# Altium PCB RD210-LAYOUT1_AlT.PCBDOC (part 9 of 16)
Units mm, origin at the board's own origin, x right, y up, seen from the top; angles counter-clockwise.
Board outline 330 x 300 mm, 6 copper layers (TOP, Mid-Layer 1, Mid-Layer 2, Mid-Layer 3, Mid-Layer 4, BOTTOM), stack 1.422 mm thick; 981 components, 463 nets, 2326 pads, 12534 vias.
Unrouted connection lines stored in the file: 6.
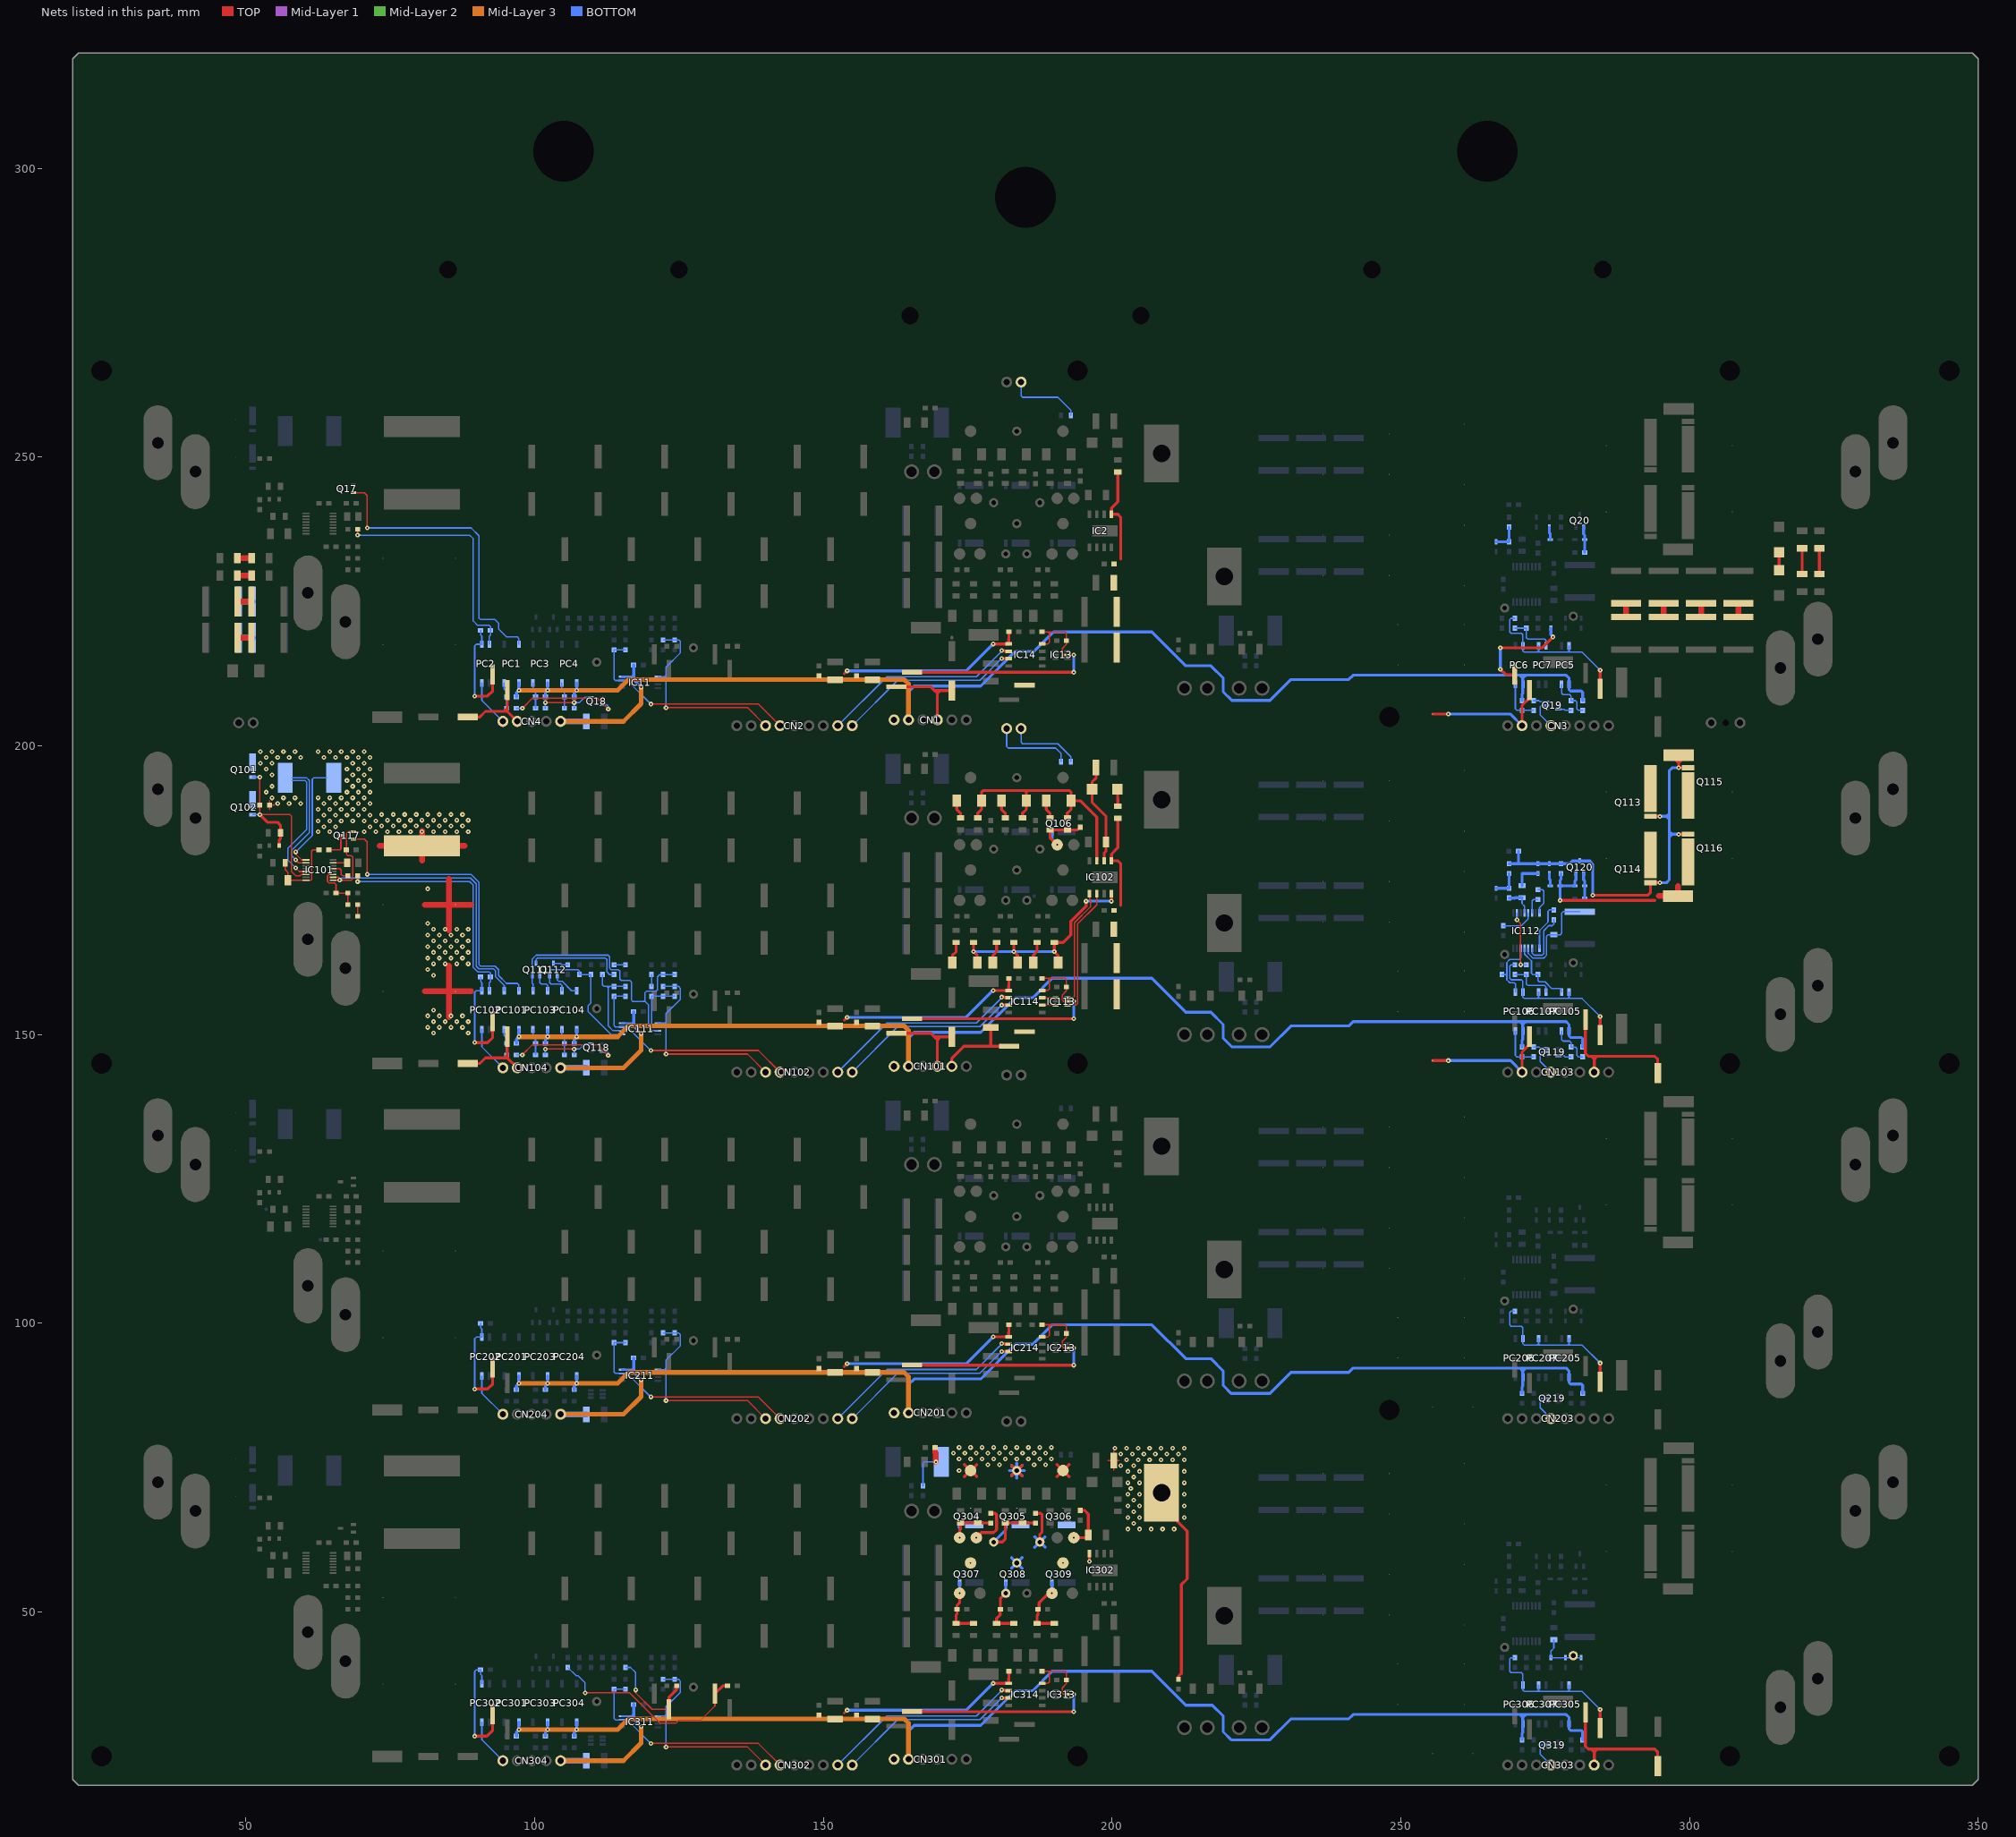
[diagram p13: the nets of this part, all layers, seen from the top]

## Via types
v1: diameter 0.8, hole 0.3, TOP to BOTTOM, 12534 vias

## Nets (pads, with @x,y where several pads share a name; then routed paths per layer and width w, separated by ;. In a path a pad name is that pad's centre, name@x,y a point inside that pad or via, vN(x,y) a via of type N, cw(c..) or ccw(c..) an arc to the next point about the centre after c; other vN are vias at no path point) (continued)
N00300323: PC1.6 Q17.1 | length 52.4
  TOP w0.25: Q17.1@68.55,243.85 Q17.1@68.6,243.85 70.525,243.85 71,243.375 v1(71,237.75)
  BOTTOM w0.25: v1(71,237.75) 89,237.75 90.375,236.375 90.375,222.125 90.625,221.875 93.125,221.875 93.75,221.25 93.75,220.25 95.125,218.875 97.02,218.875 97.27,218.625 PC1.6@97.27,217.6
N00300324: PC1.3 R66.1 R67.1 | length 4.6
  BOTTOM w0.25: PC1.3@94.715,210.9 94.715,209.91 95.15,209.475 R66.1@95.15,208.5 R67.1@95.15,206.5
N00300328: Q18.6 R67.2 | length 19
  TOP w0.25: v1(97.875,206.5) 99.625,208.25 110.875,208.25 v1(112.75,206.375)
  BOTTOM w0.25: R67.2@96.85,206.5 v1(97.875,206.5) ; Q18.6@111.775,207.1 112.5,207.1 112.75,206.85 v1(112.75,206.375)
N00300330: Q18.3 R69.1 R72.1 | length 10.2
  TOP w0.25: v1(101.85,207.5) v1(106.85,207.5)
  BOTTOM w0.25: R69.1@101.85,206.5 v1(101.85,207.5) ; R72.1@106.85,206.5 v1(106.85,207.5) 107.75,207.5 108.65,208.4 Q18.3@109.725,208.4
N00300332: PC2.2 R70.2 R71.1 | length 42.1
  TOP w0.25: v1(69.35,236.5) R70.2@69.35,237.5
  BOTTOM w0.25: v1(69.35,236.5) 88.75,236.5 89.375,235.875 89.375,221.625 90.125,220.875 92.15,220.875 92.35,220.675 R71.1@92.35,220 92.35,219.2 92.15,219 PC2.2@92.15,217.6
N00300336: PC3.3 R68.1 R69.2 | length 4.6
  BOTTOM w0.25: PC3.3@99.715,210.9 99.715,209.91 100.15,209.475 R68.1@100.15,208.5 R69.2@100.15,206.5
N00300337: D17.2 R81.2 R92.1 | length 4.8
  BOTTOM w0.5: D17.2@266.5,235.35 R81.2@268.75,235.35 R92.1@268.75,237.9
N00300339: D18.2 Q20.1 R93.2 | length 4.5
  BOTTOM w0.5: Q20.1@281.65,237.95 Q20.1@281.65,237.9 281.65,236.7 281.85,236.5 D18.2@281.85,235.75 R93.2@281.85,233.5
N00300344: PC7.2 R90.2 R91.1 | length 8.2
  BOTTOM w0.25: R91.1@269.75,220.4 R90.2@271.75,220.4 271.75,218.75 272,218.5 274.9,218.5 275.15,218.25 PC7.2@275.15,217.35
N00300350: PC4.3 R72.2 R73.1 | length 4.6
  BOTTOM w0.25: PC4.3@104.715,210.9 104.715,209.875 105.15,209.44 R73.1@105.15,208.5 R72.2@105.15,206.5
N00300353: PC5.2 R84.2 R86.1 | length 7.6
  BOTTOM w0.25: PC5.2@277.85,210.65 277.85,209.125 278.1,208.875 279.25,208.875 279.5,208.625 R84.2@279.5,207.85 280.25,207.85 280.5,207.6 280.5,206.4 280.75,206.15 R86.1@281.5,206.15
N00300354: Q19.3 R84.1 | length 2.3
  BOTTOM w0.25: Q19.3@277.275,206.35 278.25,206.35 278.45,206.15 R84.1@279.5,206.15
N00300355: PC6.2 R85.2 R87.1 | length 7.5
  BOTTOM w0.25: PC6.2@269.85,210.65 269.85,206.4 270.1,206.15 R87.1@271,206.15 R85.2@273,206.15
N00300356: Q19.6 R85.1 | length 2.3
  BOTTOM w0.25: R85.1@273,207.85 273.9,207.85 274.1,207.65 Q19.6@275.225,207.65
N00300360: D19.2 D21.2 | length 2.2
  BOTTOM w0.5: D19.2@275.75,237.9 275.75,236.875 275.9,236.725 D21.2@275.9,235.75
N00300362: C1.1 C2.2 | length 2.5
  TOP w1: C1.1@48.525,232.5 C2.2@50.975,232.5
N00300363: C3.1 C4.2 | length 2.5
  TOP w1: C3.1@48.525,229.5 C4.2@50.975,229.5
N00300364: C5.1 C6.2 | length 2.4
  TOP w1: C5.1@48.55,225 C6.2@50.95,225
N00300365: C7.1 C8.2 | length 2.4
  TOP w1: C7.1@48.55,218.75 C8.2@50.95,218.75
N00300366: C9.1 C10.2 | length 2.4
  BOTTOM w1: C9.1@48.8,225 C10.2@51.2,225
N00300367: C11.1 C12.2 | length 2.4
  BOTTOM w1: C11.1@48.8,218.75 C12.2@51.2,218.75
N00300368: C93.1 C94.2 | length 2.4
  TOP w1: C94.2@302,222.3 C93.1@302,224.7
N00300370: C91.1 C92.2 | length 2.4
  TOP w1: C92.2@295.5,222.3 C91.1@295.5,224.7
N00300371: C85.1 C86.2 | length 4.5
  TOP w0.5: C86.2@319.5,229.775 C85.1@319.5,234.225
N00300372: C87.1 C88.2 | length 4.5
  TOP w0.5: C88.2@322.5,229.775 C87.1@322.5,234.225
N00300373: C89.1 C90.2 | length 2.4
  TOP w1: C90.2@289,222.3 C89.1@289,224.7
N00300374: C95.1 C96.2 | length 2.4
  TOP w1: C96.2@308.5,222.3 C95.1@308.5,224.7
N00300375: D15.2 D16.2 | length 3.1
  TOP w0.5: D16.2@315.5,230.45 D15.2@315.5,233.55
N00300376: CN5.1 R5111.2 | length 12.9
  BOTTOM w0.25: CN5.1@184.25,263 184.25,260.625 184.5,260.375 190.604,260.375 192.85,258.129 R5111.2@192.85,257.25
N00300386: C71.1 CN3.7 CN15.1 | length 23.1
  TOP w0.5: C71.1@255.5,205.5 v1(258.25,205.5) ; CN3.7@271,203.5 271,207 272.27,208.27 CN15.1@272.27,209.65 CN15.1@272.27,209.75
  BOTTOM w0.5: v1(258.25,205.5) 269,205.5 CN3.7@271,203.5
N00300392: C97.1 CN4.2 CN13.1 | length 14.1
  TOP w0.5: C97.1@88.4,205 90.5,205 91.48,205.98 94.77,205.98 ; CN13.1@95.27,209.65 95.27,206.48 ; CN4.2@97,204.25 95.27,205.98 ; 94.77,205.98 95.27,205.98 ; 94.77,205.98 95.27,206.48 ; 95.27,205.98 95.27,206.48
N00300394: C98.1 CN1.4 CN11.1 | length 15.9
  TOP w0.5: CN11.1@162.65,210.23 168.62,210.23 169.25,209.6 ; CN1.4@169.75,204.5 169.75,209.1 ; C98.1@172.25,209.6 170.25,209.6 ; 169.25,209.6 170.25,209.6 ; 169.25,209.6 169.75,209.1 ; 169.75,209.1 170.25,209.6
N00400003: Q106.G R116.2 R117.2 R118.1 TP126.1 | length 11.1
  TOP w0.5: v1(190.5,182.875) 189.25,184.125 R116.2@189.25,185.45 R117.2@192.25,185.45 194.05,185.45 R118.1@194.5,185.9
  BOTTOM w0.5: Q106.G@189.595,185.1 189.595,183.78 v1(190.5,182.875)
N00400005: CN323.1 D311.2 D312.2 D313.2 R360.1 | length 8.8
  BOTTOM w0.25: R360.1@276.5,45.2 276.5,43.75 276,43.25 D311.2@276,42.1 D312.2@278.5,42.1 279.525,42.1 CN323.1@279.875,42.45 280.225,42.1 D313.2@281.25,42.1
N00400018: C176.1 IC111.2 R152.2 R153.1 | length 10.3
  BOTTOM w0.25: IC111.2@121.35,151.325 120.5,151.325 120.25,151.575 R152.2@120.25,156.65 C176.1@122.25,156.65 R153.1@124.25,156.65
N00400019: C111.2 IC111.3 PC103.4 Q111.2 R150.1 | length 48.7
  BOTTOM w0.25: PC103.4@99.73,157.6 99.73,158.75 99.6,158.88 Q111.2@99.6,160.15 99.6,163.1 100.25,163.75 112.75,163.75 113,163.5 113,161.5 113.25,161.25 114.5,161.25 114.75,161 114.75,159.625 115,159.375 116.5,159.375 116.75,159.125 116.75,156 117,155.75 118.875,155.75 ; IC111.3@121.35,150.675 120.325,150.675 119.75,151.25 119.75,155.125 119.125,155.75 ; R150.1@124.25,160.4 C111.2@122.25,160.4 121.65,160.4 121.25,160 121.25,157.75 121,157.5 119.375,157.5 119.125,157.25 119.125,156 ; 118.875,155.75 119.125,155.75 ; 118.875,155.75 119.125,156 ; 119.125,155.75 119.125,156
N00400023: C180.1 IC111.6 R158.2 R159.1 | length 16
  BOTTOM w0.25: R158.2@111.75,160.4 111.75,158.6 112,158.35 112.5,158.35 ; IC111.6@115.15,150.675 113.575,150.675 112.75,151.5 112.75,158.1 ; R159.1@115.75,158.35 C180.1@113.75,158.35 113,158.35 ; 112.5,158.35 112.75,158.1 ; 112.5,158.35 113,158.35 ; 112.75,158.1 113,158.35
N00400024: C179.2 IC111.5 PC104.4 Q112.2 R157.1 | length 27.3
  BOTTOM w0.25: PC104.4@104.73,157.6 104.73,158.5 104.48,158.75 102.85,158.75 102.6,159 Q112.2@102.6,160.15 102.6,161 102.85,161.25 107.5,161.25 107.75,161 C179.2@107.75,160.4 R157.1@109.75,160.4 109.75,155.5 109.25,155 109.25,154 113.225,150.025 IC111.5@115.15,150.025
N00400027: C113.2 IC101.8 R101.1 R164.2 | length 13.6
  TOP w0.25: R101.1@56.8,179.75 56.8,178.575 57.275,178.1 C113.2@57.275,176.75 IC101.8@60.4,176.75 61.25,176.75 61.375,176.875 61.375,181.75 61.625,182 R164.2@62.65,182
N00400031: D102.2 D103.2 D104.2 IC102.3 R111.1 R114.1 R117.1 | length 43.8
  TOP w0.5: R111.1@176.75,187.55 176.75,188.35 177.4,189 D102.2@177.4,190.5 177.4,192 177.65,192.25 184.9,192.25 ; R114.1@184.5,187.55 184.5,188.35 185.15,189 D103.2@185.15,190.5 185.15,192 ; R117.1@192.25,187.55 192.25,188.35 192.9,189 D104.2@192.9,190.5 ; IC102.3@197.365,180.1 197.365,187.635 194.5,190.5 D104.2@192.9,190.5 ; 184.9,192.25 185.15,192 ; 184.9,192.25 185.4,192.25 ; 185.15,192 185.4,192.25 ; 185.4,192.25 192.65,192.25 192.9,192 D104.2@192.9,190.5
N00400032: D106.2 D107.2 D108.2 IC102.8 pad.@176,164.375 pad.@183,164.375 pad.@190,164.375 R121.1 R124.1 R127.1 | length 41.2
  TOP w0.5: R121.1@176,165.95 v1(176,164.375) 176.65,163.725 D106.2@176.65,162.5 ; R124.1@183,165.95 v1(183,164.375) 183.65,163.725 D107.2@183.65,162.5 ; D108.2@190.65,162.5 190.65,163.725 v1(190,164.375) R127.1@190,165.95 191.575,165.95 192.875,167.25 192.875,169.625 195.5,172.25 v1(195.5,173.1) ; v1(199.9,173.1) 199.9,173.15 199.905,173.155 IC102.8@199.905,174.4
  BOTTOM w0.5: v1(176,164.375) v1(183,164.375) v1(190,164.375) ; v1(195.5,173.1) 195.525,173.125 199.875,173.125 v1(199.9,173.1)
N00400033: C141.1 C437.1 D105.2 IC102.2 | length 17.5
  TOP w0.5: C141.1@197.225,196.25 197.225,194.425 196.55,193.75 D105.2@196.55,192.5 196.55,190.2 198.944,187.806 C437.1@198.944,183.355 198.944,181.759 198.635,181.45 IC102.2@198.635,180.1
N00400034: IC102.6 IC113.4 | length 22.3
  TOP w0.25: IC113.4@192.275,155.1 193.75,155.1 194,155.35 194,169.125 197.365,172.49 IC102.6@197.365,174.4
N00400035: IC102.5 IC113.6 | length 20.3
  TOP w0.25: IC113.6@192.275,156.4 193.25,156.4 193.5,156.65 193.5,169.375 196.25,172.125 196.25,173.375 196.095,173.53 IC102.5@196.095,174.4
N00400036: C114.1 IC101.15 | length 2.4
  TOP w0.25: IC101.15@65.1,179.75 C114.1@67.525,179.75
N00400040: CN319.2 R347.1 R348.1 | length 17.2
  TOP w0.25: v1(117.5,36.5) 117.5,36 120.35,33.15 CN319.2@123.27,33.15
  TOP w0.5: CN319.2@123.27,33.15 123.27,35.27 124.6,36.6 R347.1@124.6,37.25
  BOTTOM w0.25: R348.1@115.75,40.4 116.6,40.4 117.5,39.5 v1(117.5,36.5)
N00400041: CN318.2 R355.1 R356.1 | length 36.6
  TOP w0.25: v1(108.75,36) 116.471,36 121.736,30.736 124.486,30.736 125,31.25 128.75,31.25 131.23,33.73 CN318.2@131.23,35.85
  TOP w0.5: CN318.2@131.23,35.85 132.63,37.25 R355.1@133.4,37.25
  BOTTOM w0.25: R356.1@105.75,40.4 107.15,39 107.5,39 108.75,37.75 v1(108.75,36)
N00400042: C116.1 C117.1 IC101.1 L101.1 R108.2 | length 72.6
  TOP w0.25: v1(58.625,181.625) 58.625,181.25 59.625,180.25 IC101.1@60.4,180.25
  TOP w1: 73.15,182.7 L101.1@80.5,182.7 ; 80.5,180.15 L101.1@80.5,182.7 ; v1@80.5,185.25 v1(80.5,185.125) L101.1@80.5,182.7 ; 81,157.5 85.15,157.5 ; 81,172.5 85.15,172.5 ; 85.15,153.043 85.15,157.5 ; 85.15,161.957 85.15,157.5 ; 85.15,168.043 85.15,172.5 ; 85.15,176.957 85.15,172.5 ; 87.85,182.7 L101.1@80.5,182.7 ; 89,157.5 C117.1@86.3,157.5 85.15,157.5 ; 89,172.5 C116.1@86.3,172.5 85.15,172.5
  BOTTOM w0.25: v1(58.625,181.625) 61.5,184.5 61.5,194.25 61.75,194.5 R108.2@64,194.5
  other v1: 82.5,150.25 88.5,150.25 81.5,151.25 83.5,151.25 85.5,151.25 87.5,151.25 82.5,152.25 84.5,152.25 86.5,152.25 88.5,152.25 81.5,153.25 83.5,153.25 85.5,153.25 87.5,153.25 82.5,154.25 82.5,160.25 81.5,161.25 82.5,162.25 84.5,162.25 86.5,162.25 88.5,162.25 81.5,163.25 83.5,163.25 85.5,163.25 87.5,163.25 82.5,164.25 84.5,164.25 86.5,164.25 88.5,164.25 81.5,165.25 83.5,165.25 85.5,165.25 87.5,165.25 82.5,166.25 84.5,166.25 86.5,166.25 88.5,166.25 81.5,167.25 83.5,167.25 85.5,167.25 87.5,167.25 82.5,168.25 84.5,168.25 86.5,168.25 88.5,168.25 81.5,169.25 81.5,175.25 62.5,185.125 64.5,185.125 70.5,185.125 72.5,185.125 74.5,185.125 76.5,185.125 78.5,185.125 82.5,185.125 84.5,185.125 86.5,185.125 88.5,185.125 63.5,186 65.5,186 71.5,186 73.5,186.125 75.5,186.125 77.5,186.125 79.5,186.125 81.5,186.125 83.5,186.125 85.5,186.125 87.5,186.125 62.5,187 64.5,187 66.5,187 68.5,187 70.5,187 72.5,187 74.5,187.125 76.5,187.125 78.5,187.125 80.5,187.125 82.5,187.125 84.5,187.125 86.5,187.125 88.5,187.125 63.5,188 65.5,188 67.5,188 69.5,188 71.5,188 73.5,188.125 75.5,188.125 77.5,188.125 79.5,188.125 81.5,188.125 83.5,188.125 85.5,188.125 87.5,188.125 62.5,189 64.5,189 66.5,189 68.5,189 70.5,189 63.5,190 65.5,190 67.5,190 69.5,190 71.5,190 62.5,191 64.5,191 66.5,191 68.5,191 70.5,191 67.5,192 69.5,192 71.5,192 68.5,193 70.5,193 67.5,194 69.5,194 71.5,194 68.5,195 70.5,195 67.5,196 69.5,196 71.5,196 68.5,197 70.5,197 63.5,198 65.5,198 67.5,198 69.5,198 71.5,198 62.5,199 64.5,199 66.5,199 68.5,199 70.5,199
N00400043: IC101.2 IC101.5 Q101.S Q102.S R107.2 R108.1 | length 44.3
  TOP w0.25: 54.1,188.975 R107.2@54.1,189.75 ; 54.1,190.525 R107.2@54.1,189.75 ; 54.925,189.75 R107.2@54.1,189.75 ; v1(58.625,178.875) 59.25,178.25 IC101.5@60.4,178.25 ; v1(58.625,180.25) 59.125,179.75 IC101.2@60.4,179.75
  BOTTOM w0.25: R108.1@58,194 60.25,194 60.5,193.75 60.5,185.5 57.25,182.25 57.25,180.25 v1(58.625,178.875) ; R108.1@58,194.5 60.5,194.5 61,194 61,185 57.875,181.875 57.875,181 v1(58.625,180.25)
  other v1: 55.5,190 57.5,190 59.5,190 54.5,191 56.5,191 58.5,191 53.5,192 54.5,193 54.5,195 53.5,196 52.5,197 54.5,197 53.5,198 55.5,198 57.5,198 59.5,198 52.5,199 54.5,199 56.5,199 58.5,199
N00400044: D323.2 IC101.6 Q101.G Q102.G R107.1 R435.1 | length 35.1
  TOP w0.25: v1(52.4,194.595) R107.1@52.4,189.75 v1(52.4,188.095) 57.625,188.095 57.875,187.845 57.875,178.25 58.625,177.5 59.375,177.5 59.625,177.75 IC101.6@60.4,177.75
  TOP w0.5: v1(52.4,188.095) 53.711,186.784 55.467,186.784 55.975,186.276 R435.1@55.975,184.942 55.975,183.936 55.775,183.736 D323.2@55.775,182.72
  BOTTOM w0.25: Q102.G@51.15,188.095 v1(52.4,188.095) ; Q101.G@51.15,194.595 v1(52.4,194.595)
N00400045: D107.1 R123.1 | length 3.7
  TOP w0.5: D107.1@179.35,162.5 179.35,163.725 180,164.375 R123.1@180,165.95
N00400046: D105.1 R109.2 | length 3
  TOP w0.5: D105.1@200.95,192.5 200.95,191 201,190.95 R109.2@201,189.55
N00400047: D102.1 R110.1 | length 3.2
  TOP w0.5: D102.1@173.1,190.5 173.1,189 173.75,188.35 R110.1@173.75,187.55
N00400049: D103.1 R113.1 | length 3.2
  TOP w0.5: D103.1@180.85,190.5 180.85,189 181.5,188.35 R113.1@181.5,187.55
N00400050: D104.1 R116.1 | length 3.2
  TOP w0.5: D104.1@188.6,190.5 188.6,189 189.25,188.35 R116.1@189.25,187.55
N00400051: D106.1 R120.1 | length 3.7
  TOP w0.5: D106.1@172.35,162.5 172.35,163.725 173,164.375 R120.1@173,165.95
N00400052: D108.1 R126.1 | length 3.7
  TOP w0.5: D108.1@186.35,162.5 186.35,163.725 187,164.375 R126.1@187,165.95
N00400056: CN332.1 Q308.G R323.2 R324.2 R325.1 | length 10.7
  TOP w0.5: CN332.1@181.595,53.25 180.65,52.305 R325.1@180.65,50.5 180.625,50.475 180.625,49.5 180,48.875 R323.2@180,48.05 R324.2@183,48.05
  BOTTOM w0.5: CN332.1@181.595,53.25 Q308.G@181.595,55.1
N00400057: CN329.1 Q305.G R313.2 R314.2 R315.1 | length 14.1
  TOP w0.5: CN329.1@179.5,62.125 181,62.125 181.5,62.625 R313.2@181.5,65.45 R314.2@184.5,65.45 186.7,65.45 R315.1@186.75,65.4
  BOTTOM w0.5: CN329.1@179.5,62.125 181.595,64.22 Q305.G@181.595,65.1
N00400060: C441.1 CN121.1 D119.1 D120.1 Q113.1 Q114.1 Q115.1 Q116.1 Q120.3 R163.2 R192.2 | length 75.2
  TOP w0.5: v1(283.25,174.125) 292.75,174.125 293.25,174.625 Q114.1@293.25,176.3 v1(294.875,176.3) ; Q113.1@293.25,187.8 v1(294.875,187.8) ; v1(298.125,184.7) Q116.1@299.75,184.7 ; Q115.1@299.75,196.2 v1(298.125,196.2) 298.125,197 ; 298.125,197 CN121.1@298.125,198.375 ; 298.125,197 297.5,197.625 297.5,198.375 CN121.1@298.125,198.375 ; 298.125,197 298.75,197.625 298.75,198.375 CN121.1@298.125,198.375
  BOTTOM w0.5: R192.2@268.75,179.6 270.405,179.6 ; C441.1@270.405,181.775 270.405,179.6 ; v1(283.25,174.125) 283.25,179.55 282.75,180.05 279.7,180.05 279.25,179.6 R163.2@277.75,179.6 D119.1@275.75,179.6 D120.1@273.75,179.6 270.405,179.6 ; v1(294.875,176.3) 296,176.3 296.5,176.8 296.5,184.2 ; v1(294.875,187.8) 296,187.8 ; v1(298.125,184.7) 297,184.7 ; v1(298.125,196.2) 297,196.2 296.5,195.7 296.5,188.3 ; 296,187.8 296.5,188.3 ; 296,187.8 296.5,187.3 ; 296.5,184.2 296.5,185.2 ; 296.5,184.2 297,184.7 ; 296.5,185.2 296.5,187.3 ; 296.5,185.2 297,184.7 ; 296.5,187.3 296.5,188.3
N00400061: CN122.1 D118.1 D121.1 Q113.2 Q114.2 Q115.2 Q116.2 Q120.2 R163.1 | length 31
  TOP w0.5: v1(277.6,173.25) 294,173.25
  TOP w1: 294.65,174 CN122.1@298,174 298,175.75
  BOTTOM w0.5: v1(277.6,173.25) D121.1@277.6,175.75 ; R163.1@277.75,177.9 277.75,176.875 277.6,176.725 D121.1@277.6,175.75 ; Q120.2@280.35,177.95 Q120.2@280.35,177.9 280.35,176.825 280.15,176.625 D118.1@280.15,175.75 D121.1@277.6,175.75
N00400066: PC103.6 Q111.1 | length 3.7
  BOTTOM w0.25: Q111.1@100.9,160.2 Q111.1@100.9,160.15 100.9,159 101.15,158.75 102.02,158.75 102.27,158.5 PC103.6@102.27,157.6
N00400067: Q111.3 R149.2 | length 16.7
  BOTTOM w0.25: Q111.3@100.25,162.3 Q111.3@100.25,162.35 100.25,163 100.5,163.25 112.25,163.25 112.5,163 112.5,160.875 112.975,160.4 R149.2@113.75,160.4
N00400068: C342.1 CN330.1 Q304.D Q305.D Q306.D R329.2 R431.1 TP304.1 TP306.1 | length 46.8
  TOP w0.5: 174.439,73.439 TP304.1@175.5,74.5 ; 174.439,75.561 TP304.1@175.5,74.5 ; 176.561,73.439 TP304.1@175.5,74.5 ; 176.561,75.561 TP304.1@175.5,74.5 ; 182.581,73.581 CN330.1@183.5,74.5 ; 182.581,75.419 CN330.1@183.5,74.5 ; 184.419,73.581 CN330.1@183.5,74.5 ; 184.419,75.419 CN330.1@183.5,74.5 ; 190.439,73.439 TP306.1@191.5,74.5 ; 190.439,75.561 TP306.1@191.5,74.5 ; 192.561,73.439 TP306.1@191.5,74.5 ; 192.561,75.561 TP306.1@191.5,74.5
  TOP w1: R431.1@169.35,78.5 169.35,77.65 169.5,77.5 v1(169.5,76)
  Mid-Layer 1 w0.5: 182.581,73.581 CN330.1@183.5,74.5 ; 182.581,75.419 CN330.1@183.5,74.5 ; 184.419,73.581 CN330.1@183.5,74.5 ; 184.419,75.419 CN330.1@183.5,74.5
  Mid-Layer 2 w0.5: 182.581,73.581 CN330.1@183.5,74.5 ; 182.581,75.419 CN330.1@183.5,74.5 ; 184.419,73.581 CN330.1@183.5,74.5 ; 184.419,75.419 CN330.1@183.5,74.5
  Mid-Layer 3 w0.5: 182.581,73.581 CN330.1@183.5,74.5 ; 182.581,75.419 CN330.1@183.5,74.5 ; 184.419,73.581 CN330.1@183.5,74.5 ; 184.419,75.419 CN330.1@183.5,74.5
  BOTTOM w0.25: C342.1@167.25,71.85 167.25,75.75 167.5,76 v1(169.5,76)
  BOTTOM w0.5: 182.2,74.5 CN330.1@183.5,74.5 ; 183.5,73.2 CN330.1@183.5,74.5 ; 183.5,75.8 CN330.1@183.5,74.5 ; 184.8,74.5 CN330.1@183.5,74.5
  other v1: 173.5,74.5 178.5,75.5 180.5,75.5 186.5,75.5 188.5,75.5 173.5,76.5 175.5,76.5 177.5,76.5 179.5,76.5 181.5,76.5 183.5,76.5 185.5,76.5 187.5,76.5 189.5,76.5 172.5,77.5 174.5,77.5 176.5,77.5 178.5,77.5 180.5,77.5 182.5,77.5 184.5,77.5 186.5,77.5 188.5,77.5 173.5,78.5 175.5,78.5 177.5,78.5 179.5,78.5 181.5,78.5 183.5,78.5 185.5,78.5 187.5,78.5 189.5,78.5
N00400069: C341.2 C439.2 CN331.1 CN333.1 IC302.4 L302.1 Q304.S Q305.S Q306.S Q307.D Q308.D Q309.D R312.2 R315.2 R318.2 R433.1 TP307.1 TP309.1 TP314.1 TP316.1 | length 73.7
  TOP w0.25: 199.325,76.25 C341.2@200.275,76.25 ; 200.275,74.525 C341.2@200.275,76.25 ; 200.275,77.975 C341.2@200.275,76.25 ; 201.225,76.25 C341.2@200.275,76.25
  TOP w0.5: v1(176.5,62.875) 177.375,63.75 179.5,63.75 180,64.25 180,66.85 179.75,67.1 R312.2@179,67.1 ; R315.2@186.75,67.1 187.625,67.1 187.875,66.85 187.875,63.875 187.5,63.5 CN331.1@187.5,62.125 ; v1(193.375,62.875) 195.429,62.875 C439.2@195.894,63.34 195.894,66.966 195.26,67.6 R318.2@194.5,67.6 ; v1(196.095,58.75) IC302.4@196.095,60.1 ; L302.1@208.566,70.664 208.566,68.434 213,64 213,55.75 212,54.75 212,39.375 211.5,38.875 R433.1@211.5,38.35
  BOTTOM w0.5: 182.581,57.581 CN333.1@183.5,58.5 ; 182.581,59.419 CN333.1@183.5,58.5 ; 184.419,57.581 CN333.1@183.5,58.5 ; 184.419,59.419 CN333.1@183.5,58.5 ; 186.581,61.206 CN331.1@187.5,62.125 ; 186.581,63.044 CN331.1@187.5,62.125 ; 188.419,61.206 CN331.1@187.5,62.125 ; 188.419,63.044 CN331.1@187.5,62.125
  other v1: 175.5,58.5 191.5,58.5 202.75,64.375 204.75,64.375 206.75,64.375 208.75,64.375 210.75,64.375 203.75,65.375 202.75,66.375 204.75,66.375 212.5,66.375 203.75,67.375 202.75,68.375 204.75,68.375 212.5,68.375 203.75,69.375 202.75,70.375 204.75,70.375 212.5,70.375 203.25,71.375 202.75,72.375 204.75,72.375 212.5,72.375 203.75,73.375 202.75,74.375 204.75,74.375 212.5,74.375 201.5,75.375 203.75,75.375 202.5,76.375 204.5,76.375 206.5,76.375 208.5,76.375 210.5,76.375 212.5,76.375 201.5,77.375 203.5,77.375 205.5,77.375 207.5,77.375 209.5,77.375 211.5,77.375 200.5,78.375 202.5,78.375 204.5,78.375 206.5,78.375 208.5,78.375 210.5,78.375 212.5,78.375
N00400073: Q112.3 R156.2 | length 2.6
  BOTTOM w0.25: Q112.3@103.25,162.3 104.5,162.3 104.7,162.1 R156.2@105.75,162.1
N00400074: PC104.6 Q112.1 | length 4.9
  BOTTOM w0.25: Q112.1@103.9,160.2 Q112.1@103.9,160.15 103.9,159.5 104.15,159.25 104.75,159.25 106.4,157.6 PC104.6@107.27,157.6
N00400075: C115.2 IC101.11 R102.1 R103.2 | length 9.3
  TOP w0.25: IC101.11@65.1,177.75 64.375,177.75 64.125,177.5 64.125,176.5 64.375,176.25 65.35,176.25 65.6,176 R102.1@65.6,174.5 C115.2@67.65,174.5 R103.2@67.65,172.5
N00400076: IC101.9 IC101.10 PC101.4 Q117.2 R165.2 | length 61.2
  TOP w0.25: IC101.9@65.1,176.75 v1(66.25,176.75) ; IC101.10@65.1,177.25 66.125,177.25 66.25,177.125 v1(66.25,176.75) ; Q117.2@68.55,185.15 67.65,185.15 67.4,184.9 R165.2@67.4,182 67.4,181.25 67.65,181 68.25,181 68.5,180.75 68.5,177 68.25,176.75 v1(66.25,176.75)
  BOTTOM w0.25: v1(66.25,176.75) 66.625,177.125 88.875,177.125 89.875,176.125 89.875,161.875 90.375,161.375 92.875,161.375 93.25,161 93.25,160 94.73,158.52 PC101.4@94.73,157.6
N00400077: IC101.13 R170.1 | length 3.5
  TOP w0.25: IC101.13@65.1,178.75 66.25,178.75 66.5,178.5 66.5,177.75 66.75,177.5 R170.1@67.65,177.5
N00400088: D120.2 R182.2 | length 4.8
  BOTTOM w0.5: R182.2@271,175.8 271,177.9 D120.2@273.75,177.9
N00400089: IC112.12 R181.1 R182.1 | length 5.1
  BOTTOM w0.25: R182.1@271,173.7 271,172.675 271.425,172.25 IC112.12@271.425,171.05
  BOTTOM w0.5: R181.1@268.75,173.65 269.75,173.65 269.8,173.7 R182.1@271,173.7
N00400091: Q304.G R310.2 R311.2 R312.1 TP324.1 | length 10.1
  TOP w0.5: v1(173.595,62.875) 173.595,64.155 173.75,64.31 R310.2@173.75,65.45 R311.2@176.75,65.45 178.95,65.45 R312.1@179,65.4
  BOTTOM w0.5: v1(173.595,62.875) Q304.G@173.595,65.1
N00400093: C181.2 IC112.4 R160.2 | length 17.5
  BOTTOM w0.25: IC112.4@272.075,164.95 272.075,164.05 272.875,163.25 274.75,163.25 275.25,163.75 275.25,167.05 275.5,167.3 R160.2@276.5,167.3 277.625,167.3 277.875,167.55 277.875,171.05 278.125,171.3 C181.2@281,171.3
N00400095: C183.1 IC112.13 | length 5.8
  BOTTOM w0.25: C183.1@267.75,168.85 270.85,168.85 272.075,170.075 IC112.13@272.075,171.05
N00400096: C182.2 IC112.1 | length 8.1
  BOTTOM w0.25: IC112.1@274.025,164.95 274.025,168.025 275.5,169.5 275.5,171.35 275.75,171.6 C182.2@276.5,171.6
N00400097: C182.1 IC112.3 | length 10.1
  BOTTOM w0.25: IC112.3@272.725,164.95 272.725,164.125 273.1,163.75 274.5,163.75 274.75,164 274.75,168 275.625,168.875 276.25,168.875 276.5,169.125 C182.1@276.5,169.9
N00400098: C184.1 IC112.14 | length 3.2
  BOTTOM w0.25: IC112.14@272.725,171.05 272.725,173.15 272.975,173.4 C184.1@273.75,173.4
N00400099: C184.2 IC112.16 | length 5.2
  BOTTOM w0.25: C184.2@273.75,175.1 274.525,175.1 274.75,174.875 274.75,172.75 274.025,172.025 IC112.16@274.025,171.05
N00400100: IC112.6 PC106.3 R188.2 | length 11.9
  BOTTOM w0.25: R188.2@267.5,160.4 268.125,160.4 ; PC106.3@269.865,157.35 269.865,158.75 269.615,159 268.875,159 268.375,159.5 268.375,160.15 ; IC112.6@270.775,164.95 270.775,163.25 270.525,163 268.875,163 268.375,162.5 268.375,160.65 ; 268.125,160.4 268.375,160.15 ; 268.125,160.4 268.375,160.65 ; 268.375,160.15 268.375,160.65
N00400101: IC112.5 PC105.3 R189.2 | length 12.2
  BOTTOM w0.25: IC112.5@271.425,164.95 271.425,163.95 272.625,162.75 272.625,160.625 272.85,160.4 R189.2@273.75,160.4 273.75,159.375 274,159.125 275,159.125 276.125,158 277.5,158 277.865,157.635 PC105.3@277.865,157.35
N00400102: IC112.10 R190.1 | length 10.2
  TOP w0.25: v1(270.125,169.875) 270.75,169.25 v1(270.75,162.1)
  BOTTOM w0.25: v1(270.125,169.875) IC112.10@270.125,171.05 ; v1(270.75,162.1) R190.1@271.75,162.1
N00400114: R148.2 R149.1 | length 2
  BOTTOM w0.25: R149.1@113.75,162.1 R148.2@115.75,162.1
N00400115: R151.2 R152.1 | length 2
  BOTTOM w0.25: R152.1@120.25,158.35 R151.2@120.25,160.4
N00400116: R103.1 R104.2 | length 2
  TOP w0.25: R104.2@69.35,170.5 R103.1@69.35,172.5
N00400118: IC113.3 IC114.6 | length 2.3
  TOP w0.25: IC114.6@187.9,155.115 188.985,155.115 189,155.1 IC113.3@190.225,155.1
N00400120: IC113.1 IC114.7 | length 2.3
  TOP w0.25: IC114.7@187.9,156.385 189,156.385 189.015,156.4 IC113.1@190.225,156.4
N00400122: Q117.3 R164.1 | length 4.5
  TOP w0.25: R164.1@64.35,182 66.25,182 66.45,182.2 Q117.3@66.45,184.5
N00400123: PC101.6 Q117.1 | length 52.4
  TOP w0.25: Q117.1@68.55,183.85 Q117.1@68.6,183.85 70.525,183.85 71,183.375 v1(71,177.75)
  BOTTOM w0.25: v1(71,177.75) 89,177.75 90.375,176.375 90.375,162.125 90.625,161.875 93.125,161.875 93.75,161.25 93.75,160.25 95.125,158.875 97.02,158.875 97.27,158.625 PC101.6@97.27,157.6
N00400124: PC101.3 R166.1 R167.1 | length 4.6
  BOTTOM w0.25: PC101.3@94.715,150.9 94.715,149.91 95.15,149.475 R166.1@95.15,148.5 R167.1@95.15,146.5
N00400128: Q118.6 R167.2 | length 19
  TOP w0.25: v1(97.875,146.5) 99.625,148.25 110.875,148.25 v1(112.75,146.375)
  BOTTOM w0.25: R167.2@96.85,146.5 v1(97.875,146.5) ; Q118.6@111.775,147.1 112.5,147.1 112.75,146.85 v1(112.75,146.375)
N00400130: Q118.3 R169.1 R172.1 | length 10.2
  TOP w0.25: v1(101.85,147.5) v1(106.85,147.5)
  BOTTOM w0.25: R169.1@101.85,146.5 v1(101.85,147.5) ; R172.1@106.85,146.5 v1(106.85,147.5) 107.75,147.5 108.65,148.4 Q118.3@109.725,148.4
N00400132: PC102.2 R170.2 R171.1 | length 42
  TOP w0.25: v1(69.35,176.5) R170.2@69.35,177.5
  BOTTOM w0.25: v1(69.35,176.5) 88.75,176.5 89.375,175.875 89.375,161.625 90.125,160.875 92.1,160.875 92.35,160.625 R171.1@92.35,160 92.35,159.2 92.15,159 PC102.2@92.15,157.6
N00400136: PC103.3 R168.1 R169.2 | length 4.6
  BOTTOM w0.25: PC103.3@99.715,150.9 99.715,149.91 100.15,149.475 R168.1@100.15,148.5 R169.2@100.15,146.5
N00400137: D117.2 R181.2 R192.1 | length 4.8
  BOTTOM w0.5: D117.2@266.5,175.35 R181.2@268.75,175.35 R192.1@268.75,177.9
N00400139: D118.2 Q120.1 R193.2 | length 4.5
  BOTTOM w0.5: Q120.1@281.65,177.95 Q120.1@281.65,177.9 281.65,176.825 281.85,176.625 D118.2@281.85,175.75 R193.2@281.85,173.5
N00400144: PC107.2 R190.2 R191.1 | length 8.2
  BOTTOM w0.25: R191.1@269.75,160.4 R190.2@271.75,160.4 271.75,158.75 272,158.5 274.9,158.5 275.15,158.25 PC107.2@275.15,157.35
N00400150: PC104.3 R172.2 R173.1 | length 4.6
  BOTTOM w0.25: PC104.3@104.715,150.9 104.715,149.875 105.15,149.44 R173.1@105.15,148.5 R172.2@105.15,146.5
N00400153: PC105.2 R184.2 R186.1 | length 7.6
  BOTTOM w0.25: PC105.2@277.85,150.65 277.85,149.125 278.1,148.875 279.25,148.875 279.5,148.625 R184.2@279.5,147.85 280.25,147.85 280.5,147.6 280.5,146.4 280.75,146.15 R186.1@281.5,146.15
N00400154: Q119.3 R184.1 | length 2.3
  BOTTOM w0.25: Q119.3@277.275,146.35 278.25,146.35 278.45,146.15 R184.1@279.5,146.15
N00400155: PC106.2 R185.2 R187.1 | length 7.5
  BOTTOM w0.25: PC106.2@269.85,150.65 269.85,146.4 270.1,146.15 R187.1@271,146.15 R185.2@273,146.15
N00400156: Q119.6 R185.1 | length 2.3
  BOTTOM w0.25: R185.1@273,147.85 273.9,147.85 274.1,147.65 Q119.6@275.225,147.65
N00400160: D119.2 D121.2 | length 2.2
  BOTTOM w0.5: D119.2@275.75,177.9 275.75,176.875 275.9,176.725 D121.2@275.9,175.75
N00400162: CN105.2 R5211.1 | length 14.5
  BOTTOM w0.25: CN105.2@181.75,203 181.75,199.875 182,199.625 190.229,199.625 191.15,198.704 R5211.1@191.15,197.25
N00400163: CN105.1 R5211.2 | length 12.9
  BOTTOM w0.25: CN105.1@184.25,203 184.25,200.625 184.5,200.375 190.604,200.375 192.85,198.129 R5211.2@192.85,197.25
N00400173: C171.1 CN103.7 CN115.1 | length 23
  TOP w0.5: C171.1@255.5,145.5 v1(258.25,145.5) ; CN103.7@271,143.5 271,147 272.27,148.27 CN115.1@272.27,149.65
  BOTTOM w0.5: v1(258.25,145.5) 269,145.5 CN103.7@271,143.5
N00400175: C197.1 CN104.2 CN113.1 | length 14.1
  TOP w0.5: C197.1@88.4,145 90.5,145 91.48,145.98 94.77,145.98 ; CN113.1@95.27,149.65 95.27,146.48 ; CN104.2@97,144.25 95.27,145.98 ; 94.77,145.98 95.27,145.98 ; 94.77,145.98 95.27,146.48 ; 95.27,145.98 95.27,146.48
N00400176: C170.1 CN103.2 CN114.1 | length 24.8
  TOP w0.5: CN114.1@281.98,152.6 281.98,146.77 282.5,146.25 283,146.25 ; CN103.2@283.5,143.5 283.5,145.75 ; C170.1@294.5,143.35 294.5,145.75 294,146.25 284,146.25 ; 283,146.25 284,146.25 ; 283,146.25 283.5,145.75 ; 283.5,145.75 284,146.25
N00400183: C199.1 CN101.5 CN112.1 | length 15.8
  TOP w0.5: CN101.5@172.25,144.5 172.25,145.875 174.355,147.98 178.75,147.98 ; C199.1@179,151.225 179,148.23 ; CN112.1@182.15,147.98 179.25,147.98 ; 178.75,147.98 179.25,147.98 ; 178.75,147.98 179,148.23 ; 179,148.23 179.25,147.98
N00400185: C198.1 CN101.4 CN111.1 | length 15.9
  TOP w0.5: CN111.1@162.65,150.23 168.62,150.23 169.25,149.6 ; CN101.4@169.75,144.5 169.75,149.1 ; C198.1@172.25,149.6 170.25,149.6 ; 169.25,149.6 169.75,149.1 ; 169.25,149.6 170.25,149.6 ; 169.75,149.1 170.25,149.6
N00400195: C370.1 CN303.2 CN314.1 | length 24.8
  TOP w0.5: CN314.1@281.98,32.6 281.98,26.77 282.5,26.25 283,26.25 ; CN303.2@283.5,23.5 283.5,25.75 ; C370.1@294.5,23.35 294.5,25.75 294,26.25 284,26.25 ; 283,26.25 284,26.25 ; 283,26.25 283.5,25.75 ; 283.5,25.75 284,26.25
N00400196: Q307.G R320.2 R321.2 R322.1 TP327.1 | length 10.3
  TOP w0.5: v1(173.595,53.25) 173.595,51.595 173.15,51.15 R322.1@173.15,50.5 173.15,49.65 173,49.5 R320.2@173,48.05 R321.2@176,48.05
  BOTTOM w0.5: v1(173.595,53.25) Q307.G@173.595,55.1
N00400197: Q309.G R326.2 R327.2 R328.1 TP329.1 | length 11.5
  TOP w0.5: v1(189.595,53.25) 189,53.25 187.375,51.625 187.375,50.725 R328.1@187.15,50.5 187.15,49.5 187,49.35 R326.2@187,48.05 R327.2@190,48.05
  BOTTOM w0.5: v1(189.595,53.25) Q309.G@189.595,55.1
PowrGood_0-1: CN4.1 PC2.4 | length 8.2
  BOTTOM w0.25: PC2.4@90.865,210.9 90.865,207.885 CN4.1@94.5,204.25
PowrGood_0-2: CN104.1 PC102.4 | length 8.2
  BOTTOM w0.25: PC102.4@90.865,150.9 90.865,147.885 CN104.1@94.5,144.25
PowrGood_0-3: CN204.1 PC202.4 | length 8.2
  BOTTOM w0.25: PC202.4@90.865,90.9 90.865,87.885 CN204.1@94.5,84.25
PowrGood_0-4: CN304.1 PC302.4 | length 8.2
  BOTTOM w0.25: PC302.4@90.865,30.9 90.865,27.885 CN304.1@94.5,24.25
PWM_H_0-1: CN2.2 IC14.2 | length 35.1
  TOP w0.5: v1(180.875,216.5) 181.375,216.5 181.49,216.385 IC14.2@182.1,216.385
  BOTTOM w0.25: CN2.2@152.5,203.5 161,212 176.5,212 180.875,216.375 v1(180.875,216.5)
PWM_H_0-2: CN102.2 IC114.2 | length 35.1
  TOP w0.5: v1(180.875,156.5) 181.375,156.5 181.49,156.385 IC114.2@182.1,156.385
  BOTTOM w0.25: CN102.2@152.5,143.5 161,152 176.5,152 180.875,156.375 v1(180.875,156.5)
PWM_H_0-3: CN202.2 IC214.2 | length 35.1
  TOP w0.5: v1(180.875,96.5) 181.375,96.5 181.49,96.385 IC214.2@182.1,96.385
  BOTTOM w0.25: CN202.2@152.5,83.5 161,92 176.5,92 180.875,96.375 v1(180.875,96.5)
PWM_H_0-4: CN302.2 IC314.2 | length 35.1
  TOP w0.5: v1(180.875,36.5) 181.375,36.5 181.49,36.385 IC314.2@182.1,36.385
  BOTTOM w0.25: CN302.2@152.5,23.5 161,32 176.5,32 180.875,36.375 v1(180.875,36.5)
PWM_L_0-1: CN2.1 IC14.3 | length 31.9
  TOP w0.5: v1(180.875,215.115) IC14.3@182.1,215.115
  BOTTOM w0.25: CN2.1@155,203.5 162.875,211.375 177.125,211.375 180.865,215.115 v1(180.875,215.115)
PWM_L_0-2: CN102.1 IC114.3 | length 31.9
  TOP w0.5: v1(180.875,155.115) IC114.3@182.1,155.115
  BOTTOM w0.25: CN102.1@155,143.5 162.875,151.375 177.125,151.375 180.865,155.115 v1(180.875,155.115)
PWM_L_0-3: CN202.1 IC214.3 | length 31.9
  TOP w0.5: v1(180.875,95.115) IC214.3@182.1,95.115
  BOTTOM w0.25: CN202.1@155,83.5 162.875,91.375 177.125,91.375 180.865,95.115 v1(180.875,95.115)
PWM_L_0-4: CN302.1 IC314.3 | length 31.9
  TOP w0.5: v1(180.875,35.115) IC314.3@182.1,35.115
  BOTTOM w0.25: CN302.1@155,23.5 162.875,31.375 177.125,31.375 180.865,35.115 v1(180.875,35.115)
STBY_0-1: CN3.5 Q19.5 | length 5.2
  BOTTOM w0.25: Q19.5@275.225,207 274.375,207 274.125,206.75 274.125,205.375 CN3.5@276,203.5
STBY_0-2: CN103.5 Q119.5 | length 5.2
  BOTTOM w0.25: Q119.5@275.225,147 274.375,147 274.125,146.75 274.125,145.375 CN103.5@276,143.5
STBY_0-3: CN203.5 Q219.5 | length 5.2
  BOTTOM w0.25: Q219.5@275.225,87 274.375,87 274.125,86.75 274.125,85.375 CN203.5@276,83.5
STBY_0-4: CN303.5 Q319.5 | length 5.2
  BOTTOM w0.25: Q319.5@275.225,27 274.375,27 274.125,26.75 274.125,25.375 CN303.5@276,23.5
V_B0-1: C76.2 CN2.7 IC11.1 R53.2 | length 36
  TOP w0.25: v1(122.75,206.625) 136.875,206.625 CN2.7@140,203.5
  BOTTOM w0.25: IC11.1@121.35,211.975 122.5,211.975 ; C76.2@122.25,218.35 R53.2@124.25,218.35 125,218.35 125.25,218.1 125.25,216.125 122.75,213.625 122.75,212.225 ; v1(122.75,206.625) 122.75,211.725 ; 122.5,211.975 122.75,212.225 ; 122.5,211.975 122.75,211.725 ; 122.75,211.725 122.75,212.225
V_B0-2: C176.2 CN102.7 IC111.1 R153.2 | length 36.1
  TOP w0.25: v1(122.75,146.625) 136.875,146.625 CN102.7@140,143.5
  BOTTOM w0.25: IC111.1@121.35,151.975 122.5,151.975 ; C176.2@122.25,158.35 R153.2@124.25,158.35 124.9,158.35 125.25,158 125.25,156.125 122.75,153.625 122.75,152.225 ; v1(122.75,146.625) 122.75,151.725 ; CN102.7@139.875,143.5 CN102.7@140,143.5 ; 122.5,151.975 122.75,152.225 ; 122.5,151.975 122.75,151.725 ; 122.75,151.725 122.75,152.225
V_B0-3: C276.2 CN202.7 IC211.1 R253.2 | length 36
  TOP w0.25: v1(122.75,86.625) 136.875,86.625 CN202.7@140,83.5
  BOTTOM w0.25: IC211.1@121.35,91.975 122.5,91.975 ; C276.2@122.25,98.35 R253.2@124.25,98.35 124.9,98.35 125.25,98 125.25,96.125 122.75,93.625 122.75,92.225 ; v1(122.75,86.625) 122.75,91.725 ; 122.5,91.975 122.75,92.225 ; 122.5,91.975 122.75,91.725 ; 122.75,91.725 122.75,92.225
V_B0-4: C376.2 CN302.7 IC311.1 R353.2 | length 36.1
  TOP w0.25: v1(122.75,26.625) 136.875,26.625 CN302.7@140,23.5
  BOTTOM w0.25: IC311.1@121.35,31.975 122.5,31.975 ; C376.2@122.25,38.35 R353.2@124.25,38.35 124.9,38.35 125.25,38 125.25,36.125 122.75,33.625 122.75,32.225 ; v1(122.75,26.625) 122.75,31.725 ; CN302.7@139.875,23.5 CN302.7@140,23.5 ; 122.5,31.975 122.75,32.225 ; 122.5,31.975 122.75,31.725 ; 122.75,31.725 122.75,32.225
V_C0-1: C80.2 CN2.6 IC11.7 R59.2 | length 39.2
  TOP w0.25: v1(120.125,207.25) 138.75,207.25 CN2.6@142.5,203.5
  BOTTOM w0.25: R59.2@115.75,216.65 C80.2@113.75,216.65 113.75,211.575 114,211.325 IC11.7@115.15,211.325 116.05,211.325 v1(120.125,207.25)
V_C0-2: C180.2 CN102.6 IC111.7 R159.2 | length 39.2
  TOP w0.25: v1(120.125,147.25) 138.75,147.25 CN102.6@142.5,143.5
  BOTTOM w0.25: R159.2@115.75,156.65 C180.2@113.75,156.65 113.75,151.575 114,151.325 IC111.7@115.15,151.325 116.05,151.325 v1(120.125,147.25)
V_C0-3: C280.2 CN202.6 IC211.7 R259.2 | length 39.2
  TOP w0.25: v1(120.125,87.25) 138.75,87.25 CN202.6@142.5,83.5
  BOTTOM w0.25: R259.2@115.75,96.65 C280.2@113.75,96.65 113.75,91.575 114,91.325 IC211.7@115.15,91.325 116.05,91.325 v1(120.125,87.25)
V_C0-4: C380.2 CN302.6 IC311.7 R359.2 | length 39.2
  TOP w0.25: v1(120.125,27.25) 138.75,27.25 CN302.6@142.5,23.5
  BOTTOM w0.25: R359.2@115.75,36.65 C380.2@113.75,36.65 113.75,31.575 114,31.325 IC311.7@115.15,31.325 116.05,31.325 v1(120.125,27.25)
VDDA-1: C77.2 C78.2 CN4.5 IC11.8 | length 29.3
  Mid-Layer 3 w0.8: CN4.5@104.5,204.25 115.375,204.25 118.425,207.3 v1(118.425,210.2)
  BOTTOM w0.35: IC11.8@115.15,211.975 116.9,211.975
  BOTTOM w0.5: C77.2@117.15,214 117.15,212.225 ; v1(118.425,210.2) 117.15,211.475 117.15,211.725 ; 117.15,211.725 116.9,211.975 117.15,212.225 ; 117.15,211.725 117.15,212.225
  BOTTOM w1: CN4.5@104.5,204.25 C78.2@108.975,204.25
VDDA-2: C177.2 C178.2 CN104.5 IC111.8 | length 29.3
  Mid-Layer 3 w0.8: CN104.5@104.5,144.25 115.375,144.25 118.425,147.3 v1(118.425,150.2)
  BOTTOM w0.35: IC111.8@115.15,151.975 116.9,151.975
  BOTTOM w0.5: C177.2@117.15,154 117.15,152.225 ; v1(118.425,150.2) 117.15,151.475 117.15,151.725 ; 117.15,151.725 117.15,152.225 ; 117.15,151.725 116.9,151.975 117.15,152.225
  BOTTOM w1: CN104.5@104.5,144.25 C178.2@108.975,144.25
VDDA-3: C277.2 C278.2 CN204.5 IC211.8 | length 29.3
  Mid-Layer 3 w0.8: CN204.5@104.5,84.25 115.375,84.25 118.425,87.3 v1(118.425,90.2)
  BOTTOM w0.35: IC211.8@115.15,91.975 116.9,91.975
  BOTTOM w0.5: C277.2@117.15,94 117.15,92.225 ; v1(118.425,90.2) 117.15,91.475 117.15,91.725 ; 117.15,91.725 117.15,92.225 ; 117.15,91.725 116.9,91.975 117.15,92.225
  BOTTOM w1: CN204.5@104.5,84.25 C278.2@108.975,84.25
VDDA-4: C377.2 C378.2 CN304.5 IC311.8 | length 29.3
  Mid-Layer 3 w0.8: CN304.5@104.5,24.25 115.375,24.25 118.425,27.3 v1(118.425,30.2)
  BOTTOM w0.35: IC311.8@115.15,31.975 116.9,31.975
  BOTTOM w0.5: C377.2@117.15,34 117.15,32.225 ; v1(118.425,30.2) 117.15,31.475 117.15,31.725 ; 117.15,31.725 117.15,32.225 ; 117.15,31.725 116.9,31.975 117.15,32.225
  BOTTOM w1: CN304.5@104.5,24.25 C378.2@108.975,24.25
VDDIO-1: C72.1 C73.1 C100.2 CN1.1 IC14.1 | length 32.7
  TOP w0.5: 153.625,212.5 v1(154.125,213) ; v1(179.405,217.655) IC14.1@182.1,217.655 182.1,218.5 182.15,218.55 C100.2@182.15,219.75
  BOTTOM w0.5: v1(154.125,213) 174.75,213 v1(179.405,217.655)
VDDIO-2: C110.2 C172.1 C173.1 CN101.1 IC114.1 | length 32.7
  TOP w0.5: 153.625,152.5 v1(154.125,153) ; v1(179.405,157.655) IC114.1@182.1,157.655 182.1,158.5 182.15,158.55 C110.2@182.15,159.75
  BOTTOM w0.5: v1(154.125,153) 174.75,153 v1(179.405,157.655)
VDDIO-3: C210.2 C272.1 C273.1 CN201.1 IC214.1 | length 32.7
  TOP w0.5: 153.625,92.5 v1(154.125,93) ; v1(179.405,97.655) IC214.1@182.1,97.655 182.1,98.5 182.15,98.55 C210.2@182.15,99.75
  BOTTOM w0.5: v1(154.125,93) 174.75,93 v1(179.405,97.655)
VDDIO-4: C310.2 C372.1 C373.1 CN301.1 IC314.1 | length 32.7
  TOP w0.5: 153.625,32.5 v1(154.125,33) ; v1(179.405,37.655) IC314.1@182.1,37.655 182.1,38.5 182.15,38.55 C310.2@182.15,39.75
  BOTTOM w0.5: v1(154.125,33) 174.75,33 v1(179.405,37.655)
VP_5R0-1: C74.1 C75.1 CN1.2 pad.@97.27,209.625 pad.@102.27,209.625 pad.@107.27,209.625 PC1.1 PC3.1 PC4.1 PC5.1 PC6.1 R66.2 R68.2 R73.2 R86.2 R87.2 | length 225.8
  Mid-Layer 3 w0.8: v1(97.27,209.625) v1(102.27,209.625) v1(107.27,209.625) 114.375,209.625 116.25,211.5 164,211.5 164.75,210.75 CN1.2@164.75,204.5
  BOTTOM w0.5: R66.2@96.85,208.5 96.85,209.205 v1(97.27,209.625) PC1.1@97.27,210.9 ; R68.2@101.85,208.5 101.85,209.205 v1(102.27,209.625) PC3.1@102.27,210.9 ; R73.2@106.85,208.5 106.85,209.205 v1(107.27,209.625) PC4.1@107.27,210.9 ; CN1.2@164.75,204.5 164.75,209.375 165.75,210.375 177.25,210.375 183.25,216.375 186.5,216.375 189.875,219.75 206.875,219.75 212.75,213.875 217.125,213.875 219.25,211.75 219.25,209.375 220.75,207.875 227.375,207.875 231,211.5 241,211.5 241.75,212.25 270.635,212.25 ; R87.2@271,207.85 271,208.99 271.135,209.125 PC6.1@271.135,210.65 271.135,211.75 ; R86.2@281.5,207.85 281.5,209.25 281.25,209.5 279.385,209.5 279.135,209.75 PC5.1@279.135,210.65 279.135,211.75 278.635,212.25 271.635,212.25 ; 270.635,212.25 271.135,211.75 ; 270.635,212.25 271.635,212.25 ; 271.135,211.75 271.635,212.25
VP_5R0-2: C174.1 C175.1 CN101.2 pad.@97.27,149.625 pad.@102.27,149.625 pad.@107.27,149.625 PC101.1 PC103.1 PC104.1 PC105.1 PC106.1 R166.2 R168.2 R173.2 R186.2 R187.2 | length 225.6
  Mid-Layer 3 w0.8: v1(97.27,149.625) v1(102.27,149.625) v1(107.27,149.625) 114.375,149.625 116.25,151.5 164,151.5 164.75,150.75 CN101.2@164.75,144.5
  BOTTOM w0.5: R166.2@96.85,148.5 96.85,149.205 v1(97.27,149.625) PC101.1@97.27,150.9 ; R168.2@101.85,148.5 101.85,149.205 v1(102.27,149.625) PC103.1@102.27,150.9 ; R173.2@106.85,148.5 106.85,149.205 v1(107.27,149.625) PC104.1@107.27,150.9 ; CN101.2@164.75,144.5 164.75,149.375 165.75,150.375 177.25,150.375 183.25,156.375 186.25,156.375 189.625,159.75 206.875,159.75 212.75,153.875 217.125,153.875 219.25,151.75 219.25,149.375 220.75,147.875 227.375,147.875 231,151.5 241,151.5 241.75,152.25 270.635,152.25 ; R187.2@271,147.85 271,148.99 271.135,149.125 PC106.1@271.135,150.65 271.135,151.75 ; 271.5,152.25 270.635,152.25 ; R186.2@281.5,147.85 281.5,149.25 281.25,149.5 279.385,149.5 279.135,149.75 PC105.1@279.135,150.65 279.135,151.75 278.635,152.25 271.635,152.25 271.135,151.75 ; 270.635,152.25 271.135,151.75
VP_5R0-3: C274.1 C275.1 CN201.2 pad.@97.27,89.625 pad.@102.27,89.625 pad.@107.27,89.625 PC201.1 PC203.1 PC204.1 PC205.1 PC206.1 R266.2 R268.2 R273.2 R286.2 R287.2 | length 225.8
  Mid-Layer 3 w0.8: v1(97.27,89.625) v1(102.27,89.625) v1(107.27,89.625) 114.375,89.625 116.25,91.5 164,91.5 164.75,90.75 CN201.2@164.75,84.5
  BOTTOM w0.5: R266.2@96.85,88.5 96.85,89.205 v1(97.27,89.625) PC201.1@97.27,90.9 ; R268.2@101.85,88.5 101.85,89.205 v1(102.27,89.625) PC203.1@102.27,90.9 ; R273.2@106.85,88.5 106.85,89.205 v1(107.27,89.625) PC204.1@107.27,90.9 ; CN201.2@164.75,84.5 164.75,89.375 165.75,90.375 177.25,90.375 183.25,96.375 186.25,96.375 189.625,99.75 206.875,99.75 212.75,93.875 217.125,93.875 219.25,91.75 219.25,89.25 220.625,87.875 227.375,87.875 231,91.5 241,91.5 241.75,92.25 270.635,92.25 ; R287.2@271,87.85 271,88.99 271.135,89.125 PC206.1@271.135,90.65 271.135,91.75 ; R286.2@281.5,87.85 281.5,89.25 281.25,89.5 279.385,89.5 279.135,89.75 PC205.1@279.135,90.65 279.135,91.75 278.635,92.25 271.635,92.25 ; 270.635,92.25 271.135,91.75 ; 270.635,92.25 271.635,92.25 ; 271.135,91.75 271.635,92.25
VP_5R0-4: C374.1 C375.1 CN301.2 PC301.1 PC303.1 PC304.1 PC305.1 PC306.1 R366.2 R368.2 R373.2 R386.2 R387.2 | length 226
  Mid-Layer 3 w0.8: v1(97.27,29.625) v1(102.27,29.625) v1(107.27,29.625) 114.375,29.625 116.25,31.5 164,31.5 164.75,30.75 CN301.2@164.75,24.5
  BOTTOM w0.5: R366.2@96.85,28.5 96.85,29.205 v1(97.27,29.625) PC301.1@97.27,30.9 ; R368.2@101.85,28.5 101.85,29.205 v1(102.27,29.625) PC303.1@102.27,30.9 ; R373.2@106.85,28.5 106.85,29.205 v1(107.27,29.625) PC304.1@107.27,30.9 ; CN301.2@164.75,24.5 164.75,29.375 165.75,30.375 177.25,30.375 183.25,36.375 186.25,36.375 189.625,39.75 206.875,39.75 212.75,33.875 217.375,33.875 219.25,32 219.25,29.25 220.625,27.875 227.375,27.875 231,31.5 241,31.5 241.75,32.25 270.635,32.25 ; R387.2@271,27.85 271,28.99 271.135,29.125 PC306.1@271.135,30.65 271.135,31.75 ; R386.2@281.5,27.85 281.5,29.25 281.25,29.5 279.385,29.5 279.135,29.75 PC305.1@279.135,30.65 279.135,31.75 278.635,32.25 271.635,32.25 ; 270.635,32.25 271.135,31.75 ; 270.635,32.25 271.635,32.25 ; 271.135,31.75 271.635,32.25
VP_5V_I0_0: C39.2 C40.2 CN11.2 IC13.5 IC14.8 | length 44.9
  TOP w0.25: C40.2@187.85,219.75 188.875,219.75 ; IC14.8@187.9,217.655 188.875,217.655 189.125,217.905 189.125,219.5 ; v1(193.375,215.75) IC13.5@192.275,215.75 191.625,215.75 191.375,216 191.375,216.875 192.1,217.6 C39.2@192.1,218.25 192.1,219.5 191.85,219.75 189.375,219.75 ; 188.875,219.75 189.125,219.5 ; 188.875,219.75 189.375,219.75 ; 189.125,219.5 189.375,219.75
  TOP w0.5: CN11.2@165.35,212.77 167.5,212.77 167.52,212.75 v1(193.375,212.75)
  BOTTOM w0.5: v1(193.375,212.75) v1(193.375,215.75)
VP_5V_I0_1: CN14.2 PC5.4 PC6.4 PC7.1 R91.2 | length 29.4
  TOP w0.5: CN14.2@284.52,209.9 v1(284.52,213.125)
  BOTTOM w0.25: R91.2@269.75,222.1 269.1,222.1 268.875,221.875 268.875,219.75 269.125,219.5 270.885,219.5 271.135,219.25 PC6.4@271.135,217.35 271.135,216.5 271.385,216.25 273.615,216.25 ; PC7.1@273.865,217.35 273.865,216.5 ; PC5.4@279.135,217.35 279.135,216.5 ; v1(284.52,213.125) 281.395,216.25 279.385,216.25 ; 273.615,216.25 274.115,216.25 ; 273.615,216.25 273.865,216.5 ; 273.865,216.5 274.115,216.25 ; 274.115,216.25 278.885,216.25 ; 278.885,216.25 279.385,216.25 ; 278.885,216.25 279.135,216.5 ; 279.135,216.5 279.385,216.25
VP_5V_I0_2: CN13.2 PC2.1 R71.2 | length 18.9
  TOP w0.5: v1(89.625,208.625) 91.855,208.625 92.73,209.5 CN13.2@92.73,212.35
  BOTTOM w0.25: v1(89.625,208.625) 89.625,217.35 89.875,217.6 PC2.1@90.865,217.6 90.865,219 90.65,219.215 R71.2@90.65,220
VP_5V_I1_0: C139.2 C140.2 CN111.2 IC113.5 IC114.8 | length 44.9
  TOP w0.25: C140.2@187.85,159.75 188.875,159.75 ; IC114.8@187.9,157.655 188.875,157.655 189.125,157.905 189.125,159.5 ; v1@193.375,155.75 v1(193.36,155.75) IC113.5@192.275,155.75 191.625,155.75 191.375,156 191.375,156.875 192.1,157.6 C139.2@192.1,158.25 192.1,159.5 191.85,159.75 189.375,159.75 ; 188.875,159.75 189.125,159.5 ; 188.875,159.75 189.375,159.75 ; 189.125,159.5 189.375,159.75
  TOP w0.5: CN111.2@165.35,152.77 167.5,152.77 167.52,152.75 v1(193.36,152.75)
  BOTTOM w0.5: v1(193.36,152.75) v1(193.36,155.75)
VP_5V_I1_1: CN114.2 PC105.4 PC106.4 PC107.1 R191.2 | length 29.4
  TOP w0.5: CN114.2@284.52,149.9 v1(284.52,153.125)
  BOTTOM w0.25: R191.2@269.75,162.1 269.1,162.1 268.875,161.875 268.875,159.75 269.125,159.5 270.885,159.5 271.135,159.25 PC106.4@271.135,157.35 271.135,156.5 271.385,156.25 273.615,156.25 ; PC107.1@273.865,157.35 273.865,156.5 ; PC105.4@279.135,157.35 279.135,156.5 ; v1(284.52,153.125) 281.395,156.25 279.385,156.25 ; 273.615,156.25 273.865,156.5 ; 273.615,156.25 274.115,156.25 ; 273.865,156.5 274.115,156.25 ; 274.115,156.25 278.885,156.25 ; 278.885,156.25 279.385,156.25 ; 278.885,156.25 279.135,156.5 ; 279.135,156.5 279.385,156.25
VP_5V_I1_2: CN113.2 PC102.1 R171.2 | length 18.9
  TOP w0.5: v1(89.625,148.625) 91.855,148.625 92.73,149.5 CN113.2@92.73,152.35
  BOTTOM w0.25: v1(89.625,148.625) 89.625,157.35 89.875,157.6 PC102.1@90.865,157.6 90.865,159 90.65,159.215 R171.2@90.65,160
VP_5V_I2_0: C239.2 C240.2 CN211.2 IC213.5 IC214.8 pad.@193.375,92.75 pad.@193.375,95.75 | length 44.9
  TOP w0.25: C240.2@187.85,99.75 188.875,99.75 ; IC214.8@187.9,97.655 188.875,97.655 189.125,97.905 189.125,99.5 ; v1(193.375,95.75) IC213.5@192.275,95.75 191.625,95.75 191.375,96 191.375,96.875 192.1,97.6 C239.2@192.1,98.25 192.1,99.5 191.85,99.75 189.375,99.75 ; 188.875,99.75 189.375,99.75 ; 188.875,99.75 189.125,99.5 ; 189.125,99.5 189.375,99.75
  TOP w0.5: CN211.2@165.35,92.77 167.5,92.77 167.52,92.75 v1(193.375,92.75)
  BOTTOM w0.5: v1(193.375,92.75) v1(193.375,95.75)
VP_5V_I2_1: CN214.2 PC205.4 PC206.4 PC207.1 R291.2 | length 29.4
  TOP w0.5: CN214.2@284.52,89.9 v1(284.52,93.125)
  BOTTOM w0.25: R291.2@269.75,102.1 269.1,102.1 268.875,101.875 268.875,99.75 269.125,99.5 270.885,99.5 271.135,99.25 PC206.4@271.135,97.35 271.135,96.5 271.385,96.25 273.615,96.25 ; PC207.1@273.865,97.35 273.865,96.5 ; PC205.4@279.135,97.35 279.135,96.5 ; v1(284.52,93.125) 281.395,96.25 279.385,96.25 ; 273.615,96.25 273.865,96.5 ; 273.615,96.25 274.115,96.25 ; 273.865,96.5 274.115,96.25 ; 274.115,96.25 278.885,96.25 ; 278.885,96.25 279.385,96.25 ; 278.885,96.25 279.135,96.5 ; 279.135,96.5 279.385,96.25
VP_5V_I2_2: CN213.2 PC202.1 R271.2 | length 18.9
  TOP w0.5: v1(89.625,88.625) 91.855,88.625 92.73,89.5 CN213.2@92.73,92.35
  BOTTOM w0.25: v1(89.625,88.625) 89.625,97.35 89.875,97.6 PC202.1@90.865,97.6 90.865,99 90.65,99.215 R271.2@90.65,100
VP_5V_I3-1: CN314.2 PC305.4 PC306.4 PC307.1 R391.2 | length 29.4
  TOP w0.5: CN314.2@284.52,29.9 v1(284.52,33.125)
  BOTTOM w0.25: R391.2@269.75,42.1 269.1,42.1 268.875,41.875 268.875,39.75 269.125,39.5 270.885,39.5 271.135,39.25 PC306.4@271.135,37.35 271.135,36.5 271.385,36.25 273.615,36.25 ; PC307.1@273.865,37.35 273.865,36.5 ; PC305.4@279.135,37.35 279.135,36.5 ; v1(284.52,33.125) 281.395,36.25 279.385,36.25 ; 273.615,36.25 273.865,36.5 ; 273.615,36.25 274.115,36.25 ; 273.865,36.5 274.115,36.25 ; 274.115,36.25 278.885,36.25 ; 278.885,36.25 279.385,36.25 ; 278.885,36.25 279.135,36.5 ; 279.135,36.5 279.385,36.25
VP_5V_I3_0: C339.2 C340.2 CN311.2 IC313.5 IC314.8 | length 44.9
  TOP w0.25: C340.2@187.85,39.75 188.875,39.75 ; IC314.8@187.9,37.655 188.875,37.655 189.125,37.905 189.125,39.5 ; v1(193.375,35.75) IC313.5@192.275,35.75 191.625,35.75 191.375,36 191.375,36.875 192.1,37.6 C339.2@192.1,38.25 192.1,39.5 191.85,39.75 189.375,39.75 ; 188.875,39.75 189.375,39.75 ; 188.875,39.75 189.125,39.5 ; 189.125,39.5 189.375,39.75
  TOP w0.5: CN311.2@165.35,32.77 167.5,32.77 167.52,32.75 v1(193.375,32.75)
  BOTTOM w0.5: v1(193.375,32.75) v1(193.375,35.75)
VP_5V_I3_2: CN313.2 PC302.1 R371.2 | length 21.2
  TOP w0.5: v1(89.625,28.5) 91.73,28.5 92.73,29.5 CN313.2@92.73,32.35
  BOTTOM w0.25: v1(89.625,28.5) 89.625,39.75 89.875,40 R371.2@90.65,40 90.65,39.215 90.865,39 PC302.1@90.865,37.6
VP_12R0_SYS_I0_0: C35.2 C36.2 C37.1 C38.1 CN12.2 IC2.1 R9.1 | length 16.8
  TOP w0.5: R9.1@201,247.45 201,242.308 199.905,241.213 IC2.1@199.905,240.1 201,240.1 201.5,239.6 201.5,232.375
VP_12R0_SYS_I0_1: CN15.2 D11.1 | length 18.2
  TOP w0.5: v1(267.25,213.25) 268.15,212.35 CN15.2@269.73,212.35 ; v1(267.25,217) 274.5,217 v1(276.375,218.875)
  BOTTOM w0.5: v1(267.25,213.25) v1(267.25,217) ; D11.1@276,220.4 276,219.25 v1(276.375,218.875)
VP_12R0_SYS_I1_0: C135.2 C136.2 C137.1 C138.1 CN112.2 IC102.1 R109.1 | length 16.8
  TOP w0.5: R109.1@201,187.45 201,182.364 199.905,181.269 IC102.1@199.905,180.1 201,180.1 201.5,179.6 201.5,172.375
